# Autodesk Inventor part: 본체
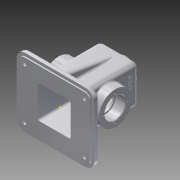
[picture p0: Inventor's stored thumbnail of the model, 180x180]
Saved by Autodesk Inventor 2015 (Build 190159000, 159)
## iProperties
Created: 2016-02
Part Number: 본체
Material: 알루미늄 6061
Document SubType Name: Modeling
Designer: Administrator
Density: 2.7 g/cm^3
Appearance: 알루미늄 - 평지
Mass: 801.895 g
Surface Area: 910.185 cm^2
Volume: 296.998 cm^3
Author: Administrator
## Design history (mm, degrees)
sketch "스케치1"
  geometry: L1 (65, -57.5)-(-65, -57.5); L2 (-65, -57.5)-(-65, 57.5); L3 (-65, 57.5)-(65, 57.5); L4 (65, 57.5)-(65, -57.5); L5 (65, -57.5)-(-65, 57.5); L6 (-65, -57.5)-(65, 57.5); 1 further point
  constraints: 12 end point, 2 midpoint, 2 parallel, 1 horizontal, 1 perpendicular
  dimensions: "d0" = 130 distance of L1.start L1.end; "d1" = 115 distance of L3.end L1.start
extrude "돌출1" new body sketch "스케치1" distance "d2" = 10; taper "d3" = 0 deg
sketch "스케치2"
  geometry: L1 (-65, -57.5)-(65, -57.5) reference; L2 (-65, 57.5)-(-65, -57.5) reference; L3 (65, 57.5)-(-65, 57.5) reference; L4 (65, -57.5)-(65, 57.5) reference; L5 (-60, 52.5)-(-60, -52.5); L6 (-60, -52.5)-(60, -52.5); L7 (60, -52.5)-(60, 52.5); L8 (60, 52.5)-(-60, 52.5); L9 (-65, -57.5)-(65, -57.5); L10 (65, -57.5)-(65, 57.5); L11 (65, 57.5)-(-65, 57.5); L12 (-65, 57.5)-(-65, -57.5); L13 (-65, -57.5)-(65, 57.5); L14 (65, -57.5)-(-65, 57.5); 1 further point
  constraints: 20 end point, 2 midpoint, 2 parallel, 1 horizontal, 1 perpendicular, 3 other
  dimensions: "d4" = 5 distance between parallel lines of L3 L8
extrude "돌출2" cut sketch "스케치2" distance "d5" = 2; taper "d6" = 0 deg
sketch "스케치3"
  geometry: L1 (-32.5, 32.5)-(32.5, 32.5); L2 (32.5, 32.5)-(32.5, -32.5); L3 (32.5, -32.5)-(-32.5, -32.5); L4 (-32.5, -32.5)-(-32.5, 32.5); L5 (-32.5, 32.5)-(32.5, -32.5); L6 (32.5, 32.5)-(-32.5, -32.5); 1 further point
  constraints: 12 end point, 2 midpoint, 2 parallel, 1 horizontal, 1 perpendicular
  dimensions: "d7" = 65 distance of L1.start L1.end; "d8" = 65 distance of L1.end L2.end
extrude "돌출3" join sketch "스케치3" distance "d9" = 100; taper "d10" = 0 deg
sketch "스케치4"
  geometry: C1 r 20 at (0, 0); 1 further point
  constraints: 1 centre point, 1 coincident
  dimensions: "d11" = 40 diameter of C1
extrude "돌출4" join sketch "스케치4" distance "d12" = 10; taper "d13" = 0 deg
sketch "스케치5"
  geometry: C1 r 27.5 at (45, 0); 1 further point
  constraints: 1 centre point
  dimensions: "d14" = 45 distance of point (0, 0) C1.centre; "d15" = 0 vertical distance of point (0, 0) C1.centre; "d16" = 55 diameter of C1
extrude "돌출5" join sketch "스케치5" stored distance "d17" = 95; taper "d18" = 0 deg
sketch "스케치6"
  geometry: L1 (-10, 52.5)-(-8, 52.5) reference; L2 (-8, 52.5)-(-8, 57.5) reference; L3 (-8, 57.5)-(0, 57.5) reference; L4 (0, 57.5)-(0, 32.5) reference; L5 (0, 32.5)-(100, 32.5) reference; L6 (100, 32.5)-(100, 20) reference; L7 (100, 20)-(110, 20) reference; L8 (110, 20)-(110, -20) reference; L9 (110, -20)-(100, -20) reference; L10 (100, -20)-(100, -32.5) reference; L11 (100, -32.5)-(0, -32.5) reference; L12 (0, -32.5)-(0, -57.5) reference; L13 (0, -57.5)-(-8, -57.5) reference; L14 (-8, -57.5)-(-8, -52.5) reference; L15 (-8, -52.5)-(-10, -52.5) reference; L16 (-10, -52.5)-(-10, 52.5) reference; L17 (0, -47.5)-(92.075, -31.265); L18 (92.075, -31.265)-(0, -31.265); L19 (0, -32.5)-(0, 32.5) reference; 1 further point
  constraints: 4 end point, 2 point on line, 1 horizontal
  dimensions: "d19" = 10 vertical distance of L13.end L17.start; "d20" = 10 deg angle of L13 L17; "d21" = 97.23843 distance of point (0, 0) L17.end
extrude "돌출6" join sketch "스케치6" stored distance "d22" = 10; taper "d23" = 0 deg
sketch "스케치7"
  geometry: 1 further point
sketch "스케치8"
  geometry: L1 (-27.5, -27.5)-(27.5, -27.5); L2 (27.5, -27.5)-(27.5, 27.5); L3 (27.5, 27.5)-(-27.5, 27.5); L4 (-27.5, 27.5)-(-27.5, -27.5); L5 (-27.5, -27.5)-(27.5, 27.5); L6 (27.5, -27.5)-(-27.5, 27.5); 1 further point
  constraints: 12 end point, 2 midpoint, 2 parallel, 1 horizontal, 1 perpendicular
  dimensions: "d24" = 55 distance of L3.end L1.start; "d25" = 55 distance of L2.end L3.end
extrude "돌출7" cut sketch "스케치8" distance "d26" = 105; taper "d27" = 0 deg
sketch "스케치9"
  geometry: L1 (-60, -10)-(-60, -8) reference; L2 (-60, -8)-(-65, -8) reference; L3 (-65, -8)-(-65, 0) reference; L4 (-65, 0)-(-32.5, 0) reference; L5 (-32.5, 0)-(-32.5, 17.5) reference; L6 (-32.5, 17.5)-(-47.5, 17.5) reference; L7 (-47.5, 17.5)-(-47.5, 72.5) reference; L8 (-47.5, 72.5)-(-32.5, 72.5) reference; L9 (-32.5, 72.5)-(-32.5, 100) reference; L10 (-32.5, 100)-(-20, 100) reference; L11 (-20, 100)-(-20, 110) reference; L12 (-20, 110)-(20, 110) reference; L13 (20, 110)-(20, 100) reference; L14 (20, 100)-(32.5, 100) reference; L15 (32.5, 100)-(32.5, 72.5) reference; L16 (32.5, 72.5)-(47.5, 72.5) reference; L17 (47.5, 72.5)-(47.5, 17.5) reference; L18 (47.5, 17.5)-(32.5, 17.5) reference; L19 (32.5, 17.5)-(32.5, 0) reference; L20 (32.5, 0)-(65, 0) reference; L21 (65, 0)-(65, -8) reference; L22 (65, -8)-(60, -8) reference; L23 (60, -8)-(60, -10) reference; L24 (60, -10)-(27.5, -10) reference; L25 (27.5, -10)-(27.5, 95) reference; L26 (27.5, 95)-(-27.5, 95) reference; L27 (-27.5, 95)-(-27.5, -10) reference; L28 (-27.5, -10)-(-60, -10) reference; L29 (-65, 0)-(65, 0) reference; L30 (-42.5, 0)-(-42.5, 26.418); L31 (-42.5, 26.418)-(-29.871, 26.418); L32 (-29.871, 26.418)-(-29.871, 0); 1 further point
  constraints: 6 end point, 2 perpendicular, 2 point on line, 1 horizontal
  dimensions: "d28" = 15 distance between parallel lines of L30 L27; "d29" = 12.62939 distance of L30.end L31.end; "d30" = 26.41756 distance of L30.start L30.end
extrude "돌출8" join sketch "스케치9" stored distance "d31" = 6; taper "d32" = 0 deg
sketch "스케치10"
  geometry: C1 r 15 at (0, 0); A1 r 27.5 centre (0, 0) between (3, -27.336) and (-3, -27.336) reference; A2 r 27.5 centre (0, 0) between (3, -27.336) and (-3, -27.336) reference; 1 further point
  constraints: 1 centre point, 1 concentric
  dimensions: "d33" = 30 diameter of C1
extrude "돌출9" cut sketch "스케치10" stored distance "d34" = 6; taper "d35" = 0 deg
sketch "스케치11"
  geometry: C1 r 17.5 at (0, 0); A1 r 27.5 centre (0, 0) between (3, -27.336) and (-3, -27.336) reference; 1 further point
  constraints: 1 centre point, 1 concentric
  dimensions: "d36" = 35 diameter of C1
extrude "돌출10" cut sketch "스케치11" distance "d37" = 17; taper "d38" = 0 deg
fillet "모깎기1" dims "d39" = 15
fillet "모깎기2" dims "d40" = 10
sketch "스케치12"
  geometry: C1 r 7.5 at (50, 42.5); A1 r 15 centre (50, 42.5) between (65, 42.5) and (50, 57.5) reference; 1 further point
  constraints: 1 centre point, 1 concentric
  dimensions: "d41" = 15 diameter of C1
extrude "돌출11" join sketch "스케치12" distance "d42" = 3; taper "d43" = 0 deg
hole "구멍1" diameter "d46" = 6; stored, may be unused: countersink angle "d50" = 90 deg, drill point angle "d52" = 118 deg; dims "d44" = 10, "d45" = 10, "d47" = 6, "d48" = 4, "d49" = 2, "d51" = 8
fillet "모깎기3" dims "d53" = 8
fillet "모깎기4" dims "d54" = 8
fillet "모깎기7" dims "d57" = 3
fillet "모깎기8" dims "d58" = 3
fillet "모깎기9" dims "d59" = 3
fillet "모깎기10" dims "d60" = 1
fillet "모깎기11" dims "d61" = 3
fillet "모깎기12" dims "d62" = 3
sketch "스케치13"
  geometry: L1 (-24.5, -55)-(24.5, -55) reference; 2 further points
  dimensions: "d63" = 0 horizontal distance of point (0, -45) point (0, 21); "d64" = 76 distance from line of L1 point (0, 21)
hole "구멍2" sketch "스케치13" at (0, 21) diameter "d65" = 3.242; stored, may be unused: countersink angle "d69" = 90 deg, drill point angle "d71" = 118 deg; dims "d66" = 8, "d67" = 4, "d68" = 2, "d70" = 10
sketch "스케치14"
  geometry: C1 r 10.5 at (0, 0); C2 r 20 at (0, 0) reference; 1 further point
  constraints: 1 centre point, 1 concentric
  dimensions: "d75" = 21 diameter of C1
extrude "돌출12" cut sketch "스케치14" distance "d76" = 48.5; taper "d77" = 0 deg
sketch "스케치15"
  geometry: 2 further points
  dimensions: "d78" = 0 horizontal distance of point (0, 0) point (0, 14.5); "d79" = 14.5 distance of point (0, 0) point (0, 14.5)
hole "구멍3" sketch "스케치15" at (0, 14.5) diameter "d80" = 2.459; stored, may be unused: countersink angle "d84" = 90 deg, drill point angle "d86" = 118 deg; dims "d81" = 7, "d82" = 4, "d83" = 2, "d85" = 9
sketch "스케치16"
  geometry: 1 further point
sketch "스케치17"
  geometry: L1 (57, -91)-(57, 0) reference; L2 (44.5, 18)-(4.5, 18) reference; 2 further points
  constraints: 1 other
  dimensions: "d90" = 32.5 distance from line of L1 point (24.5, -8); "d91" = 26 distance from line of L2 point (24.5, -8)
feature "엠보싱1" sketch "스케치17" dims "d92" = 0.5, "d93" = 0
fillet "모깎기13" dims "d94" = 0.3
chamfer "모따기1" distance "d95" = 1; stored, may be unused: second distance "d96" = 2, angle "d97" = 45 deg
chamfer "모따기2" distance "d98" = 1; stored, may be unused: second distance "d99" = 2, angle "d100" = 45 deg
fillet "모깎기14" dims "d101" = 3
fillet "모깎기15" dims "d102" = 3
fillet "모깎기16" dims "d103" = 3
feature "면 기울기1" dims angle "d104" = 5 deg
fillet "모깎기17" dims "d105" = 3
node "솔리드1"
mirror "대칭1"
mirror "대칭2"
mirror "대칭3"
mirror "대칭4"
mirror "대칭5"
mirror "대칭6"
mirror "대칭7"
pattern_circular "원형 패턴1" dims angle "d73" = 360 deg
mirror "대칭8"
pattern_circular "원형 패턴2" dims angle "d88" = 360 deg
node "투영된 루프1"
node "절단 모서리 투영1"
node "절단 모서리 투영2"
